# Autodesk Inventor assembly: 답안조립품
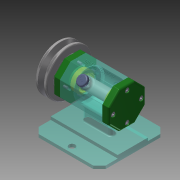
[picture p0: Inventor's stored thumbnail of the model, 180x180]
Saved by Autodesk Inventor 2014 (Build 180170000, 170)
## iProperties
Created: 2018-06
Part Number: 답안조립품
Document SubType Name: Assembly
Designer: kh
Author: kh
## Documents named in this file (16)
- C:\Users\kh\Desktop\480607V1022\답안조립품.iam
- C:\Users\kh\Desktop\480607V1022\본체.ipt
- C:\Users\kh\Desktop\480607V1022\V벨트풀리.ipt
- C:\Users\kh\Desktop\480607V1022\고무캡.ipt
- C:\Users\kh\Desktop\480607V1022\너트 M8.ipt
- 너트 M8.ipt
- C:\Users\kh\Desktop\480607V1022\뒤커버.ipt
- C:\Users\kh\Desktop\480607V1022\베어링 15x32x9.ipt
- C:\Users\kh\Desktop\480607V1022\볼트 M4x12.ipt
- C:\Users\kh\Desktop\480607V1022\스프링와셔 8.ipt
- C:\Users\kh\Desktop\480607V1022\앞커버.ipt
- C:\Users\kh\Desktop\480607V1022\오일 실 15 25 7.ipt
- C:\Users\kh\Desktop\480607V1022\와셔 8x17.ipt
- C:\Users\kh\Desktop\480607V1022\축.ipt
- C:\Users\kh\Desktop\480607V1022\키 3x3x12.ipt
- 키 3x3x12.ipt
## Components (2 placed, 2 different names)
1. V벨트풀리:1 — Insert:9, Mate:5, Mate:6, Insert:10
2. 고무캡:1 — Insert:14
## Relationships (5: Insert 3, Mate 2)
- Insert:9: V벨트풀리:1
- Mate:5: V벨트풀리:1
- Mate:6: V벨트풀리:1
- Insert:10: V벨트풀리:1
- Insert:14: 고무캡:1
